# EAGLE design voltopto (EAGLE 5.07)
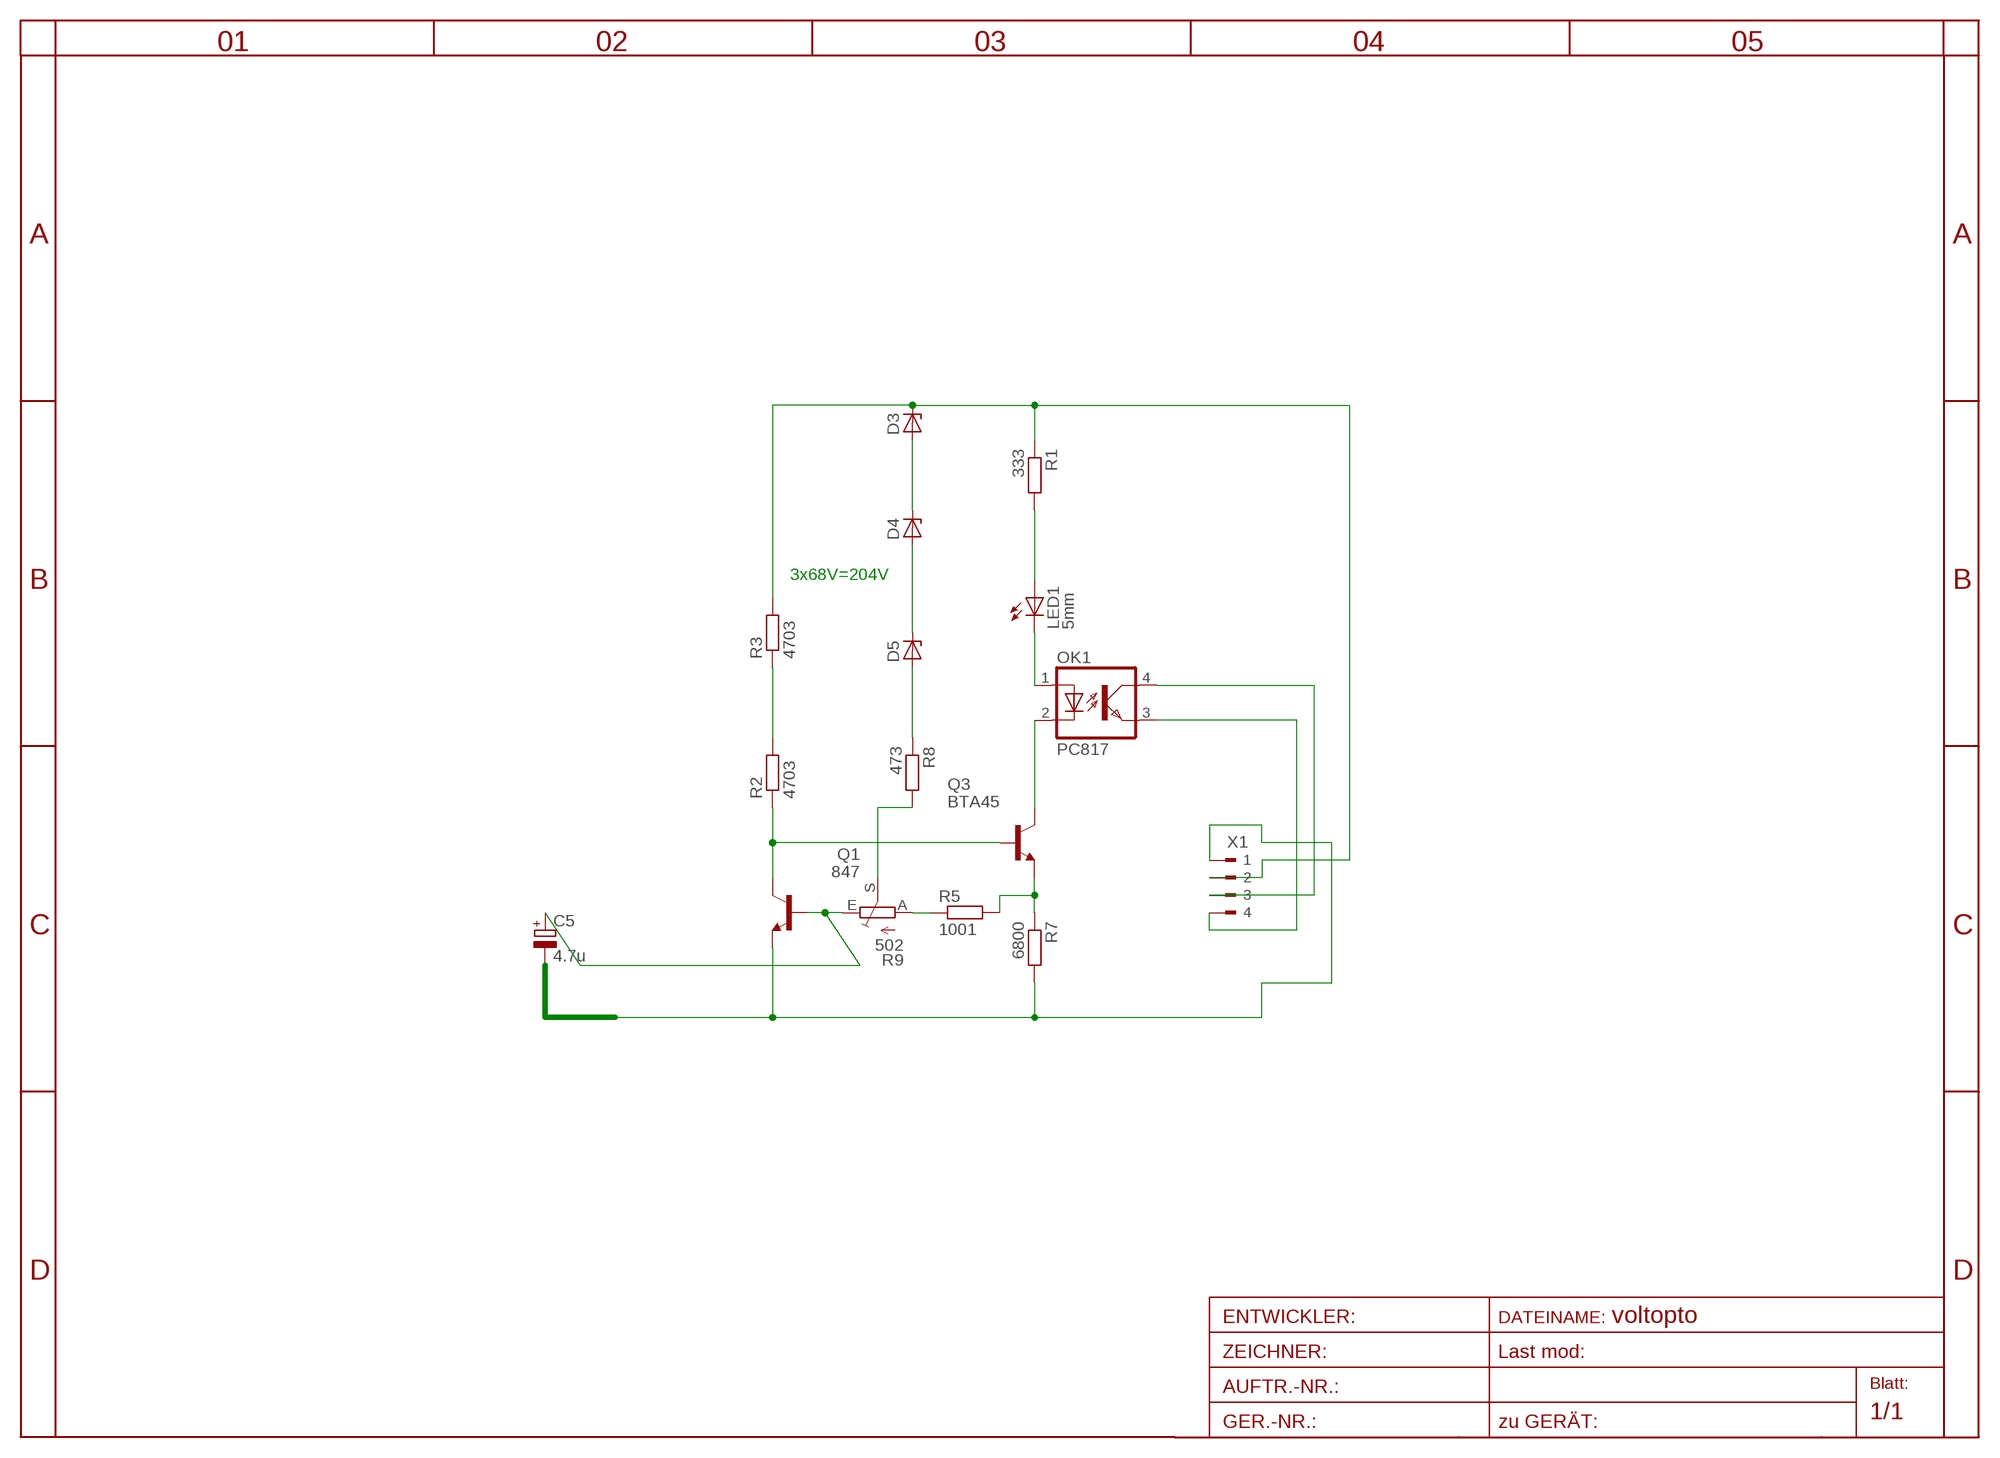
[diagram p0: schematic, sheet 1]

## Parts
C5  4.7u  CPOL-EUSMCA  [SMC_A]
D3  ZENER-DIODESOD80C  [SOD80C]
D4  ZENER-DIODESOD80C  [SOD80C]
D5  ZENER-DIODESOD80C  [SOD80C]
LED1  5mm  LED5MM  [LED5MM]
OK1  PC817  [DIL04]
Q1  847  BC848ALT1SMD  [SOT23]
Q3  BTA45  BC848ALT1SMD  [SOT23]
R1  333  R-EU_R1206  [R1206]
R2  4703  R-EU_R1206  [R1206]
R3  4703  R-EU_R1206  [R1206]
R5  1001  R-EU_R1206  [R1206]
R7  6800  R-EU_R1206  [R1206]
R8  473  R-EU_R1206  [R1206]
R9  502  TRIM_EU-S64W  [S64W]
X1  90-4  [90-4]

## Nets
A: LED1.A R1.2
AP: R5.1 R9.A
E: C5.+ Q1.1(B) R9.E
IN: D3.C R1.1 R3.2 X1.2
K: LED1.K(C) OK1.1(A)
N$3: R2.2 R3.1
N$8: Q3.2(E) R5.2 R7.1
N$13: D5.A R8.1
N$14: D4.A D5.C
N$15: D3.A D4.C
N$17: OK1.3(EMIT) X1.4
N$20: Q1.3(C) Q3.1(B) R2.1
N$21: OK1.2(C) Q3.3(C)
OUT-: OK1.4(COL) X1.3
S: R8.2 R9.S
V-: C5.- Q1.2(E) R7.2 X1.1

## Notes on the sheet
- 3x68V=204V

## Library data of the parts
C5 = rcl:CPOL-EU: POLARIZED CAPACITOR, European symbol
D3-D5 = diode:ZENER-DIODE: Z-Diode
LED1 = led:LED: LED
OK1 = optocoupler:PC817: SHARP OPTO COUPLER
Q1 Q3 = transistor-npn:BC848*: NPN Transistor
R1-R3 R5 R7 R8 = rcl:R-EU_: RESISTOR, European symbol
R9 = pot:TRIM_EU-: POTENTIOMETER
X1 = con-weidmueller-sl35:90-4: WEIDMUELLER CLAMP CONNECTOR

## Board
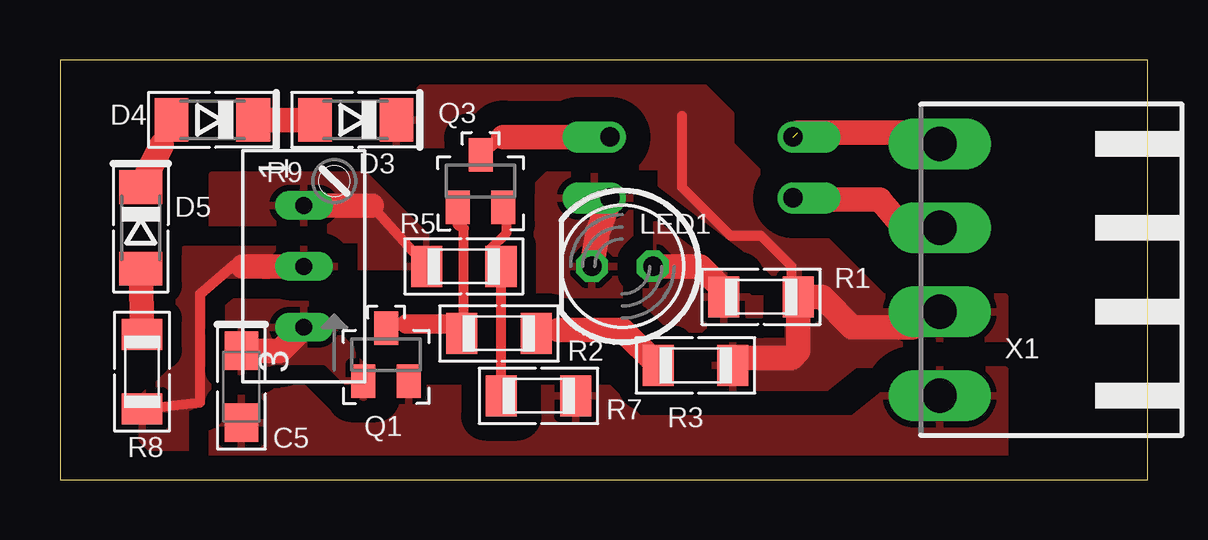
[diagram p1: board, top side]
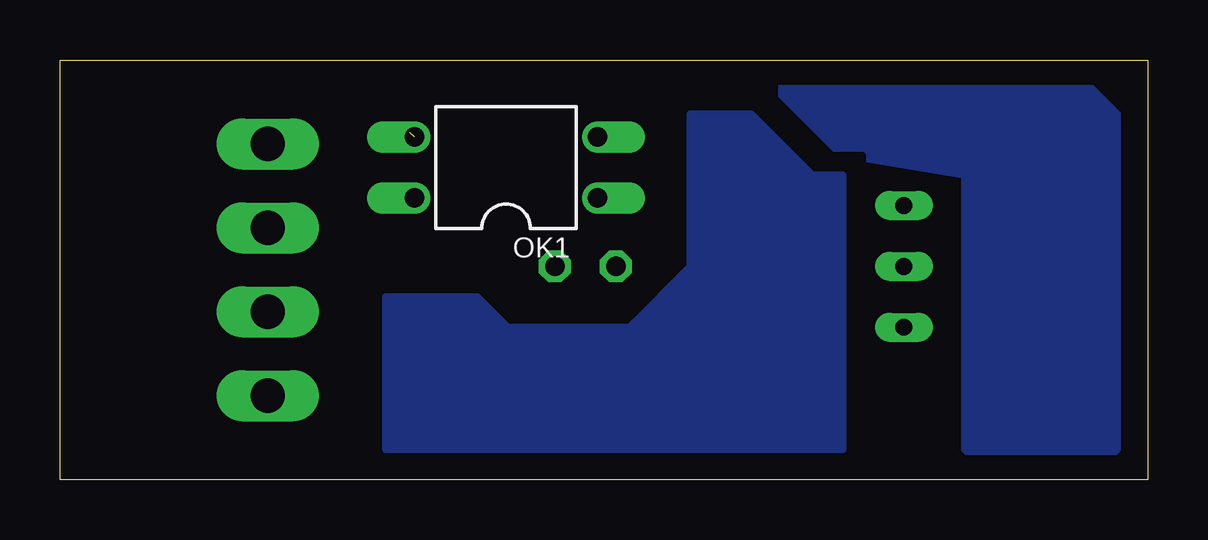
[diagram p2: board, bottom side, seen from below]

Size 45.32 x 17.5 mm. Coordinates in mm from the lower left corner, seen from the top.
Outline: 0,0 45.32,0 45.32,17.5 0,17.5 0,0
Copper layers (1*16): Top 0.035mm / dielectric 1.5mm / Bottom 0.035mm
Design rules "default *": minimum track width 10mil, minimum drill 20mil, track to track 8mil, track to pad 8mil, pad to pad 8mil, via to via 8mil, smd to smd 8mil, copper to edge 40mil, drill to drill 8mil, minimum pad ring 10mil, minimum via ring 8mil, stop-mask expansion 4mil, vias tented up to drill 0mil, thermal gap 10mil

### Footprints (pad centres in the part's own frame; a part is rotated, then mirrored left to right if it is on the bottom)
SMC_A = smd 1.6 x 1.4: + -1.5,0; - 1.5,0
SOD80C = smd 1.4 x 1.8: A 1.7,0; C -1.7,0
LED5MM = drill 0.813 octagon: A -1.27,0; K 1.27,0
DIL04 = drill 0.813 offset: 1 -1.27,-3.81; 2 1.27,-3.81; 3 1.27,3.81; 4 -1.27,3.81
SOT23 = smd 1 x 1.4: 1 -0.95,-1.1; 2 0.95,-1.1; 3 0,1.1
R1206 = smd 1.3 x 1.7: 1 -1.55,0; 2 1.55,0
S64W = drill 0.7 long: A 2.54,1.27; E -2.54,1.27; S 0,1.27
90-4 = drill 1.422 long: 1 -5.25,5.25; 2 -1.75,5.25; 3 1.75,5.25; 4 5.25,5.25

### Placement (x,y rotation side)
C5  7.56,3.87 270 top
D3  12.32,15 180 top
D4  6.35,15 180 top
D5  3.37,10.5 270 top
LED1  23.43,8.89 180 top
OK1  26.73,13.02 90 bottom
Q1  13.59,5.21 0 top
Q3  17.53,12.45 0 top
R1  29.21,7.62 180 top
R2  18.29,6.1 0 top
R3  26.48,4.76 0 top
R5  16.83,8.89 0 top
R7  19.94,3.49 0 top
R8  3.42,4.5 270 top
R9  11.43,8.89 90 top
X1  41.91,8.75 90 top

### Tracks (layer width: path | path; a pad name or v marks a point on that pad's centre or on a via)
A
  Top 1.016: R1.2 27.66,7.9 26.67,8.89 LED1.A
  pour Top (isolate 0.813, rank 4): 25.4,11.43 26.23,11.43 29.27,8.38 29.27,6.73 28.83,6.29 25.08,6.29 24.13,7.24 24.13,10.86 24.57,11.3
AP
  Top 0.406: 13,11.43 R5.1
  Top 1.016: R9.A 13,11.43
  pour Top (isolate 0.813, rank 4): 6.35,12.7 12.7,12.7 15.24,10.16 15.24,8.89 12.7,8.89 11.43,8.89 10.16,10.16 6.35,10.16
E
  Top 1.016: C5.+ 9.18,5.37 R9.E
  pour Top (isolate 0.813, rank 2): 7.62,7.62 9.97,7.62 12.95,4.64 12.95,3.56 12.83,3.43 9.46,3.43 8.57,4.32 7.37,4.32 6.98,4.7 6.98,7.18 7.18,7.37
IN
  Top 0.406: 25.92,15.18 25.92,12.18 27.94,10.16 29.21,10.16 30.48,8.89 30.48,7.9 R1.1
  Top 1.016: R3.2 28.35,5.08 30.48,5.08 30.76,5.36 R1.1 31.75,7.62 33.02,6.35 35.52,6.35 36.17,7 X1.2
  pour Top (isolate 1.016, rank 2): 39.37,7.62 34.29,7.62 27.94,13.97 27.94,15.24 26.67,16.51 15.24,16.51 13.97,15.24 13.97,13.97 22.86,13.97 29.21,9.14 30.35,8 30.35,5.78 27.31,5.71 27.31,4.45 27.94,2.54 31.75,2.54 35.56,5.08 39.37,5.08
K
  Top 1.016: OK1.1 22.42,10.31 LED1.K
  pour Top (isolate 0.813): 19.05,11.43 20.32,12.7 22.86,12.7 23.11,12.7 23.75,12.06 23.75,10.03 23.3,9.59 23.3,7.49 22.8,6.99 20.07,6.99 18.99,8.06
N$1
  pour Bottom (isolate 0.813, rank 4): 15.24,13.97 15.24,16.51 2.54,16.51 1.27,15.24 1.27,1.27 2.54,0 6.35,0 7.62,1.27 7.62,12.7
N$2
  pour Bottom (isolate 0.813, rank 3): 12.7,12.7 13.97,12.7 16.51,15.24 19.05,15.24 19.05,8.89 21.59,6.35 26.67,6.35 27.94,7.62 31.75,7.62 31.75,1.27 12.7,1.27
N$3
  Top 0.406: R2.2 20.6,6.39 20.32,6.22 20.76,6.25
  Top 1.016: 20.76,6.25 23.43,6.25 R3.1
N$8
  Top 0.406: R7.1 18.39,8.43 R5.2 17.93,9.61 18.61,10.29 18.61,11.22 Q3.2
N$13
  Top 1.016: R8.1 D5.A
N$14
  Top 0.406: 4.24,13.97 D4.A
  Top 1.016: D5.C 4.24,13.97
N$15
  Top 0.406: 10.65,15 D3.A
  Top 1.016: D4.C 10.65,15
N$17  (1 unrouted)
  Top 0.406: 35.37,14.48 35.85,14
  Top 1.016: 35.85,14 X1.4 | 30.75,14.48 35.37,14.48
N$20
  Top 0.406: Q3.1 16.58,10.6 16.83,10.48 16.83,6.57 R2.1 16.45,6.67 16.26,6.5 | Q1.3 14.44,6.5
  Top 0.813: 14.44,6.5 16.26,6.5
N$21
  Top 0.406: Q3.3 18.48,14.29
  Top 1.016: 18.48,14.29 OK1.2
OUT-
  Top 0.406: OK1.4 30.73,11.68
  Top 1.016: X1.3 35.16,10.5 34.16,11.68 30.73,11.68
S
  Top 0.406: R8.2 5.84,3.21 5.84,7.75 7.22,8.93 7.62,8.89
  Top 1.016: 7.62,8.89 R9.S
  pour Top (isolate 0.813, rank 3): 5.21,9.59 10.92,9.59 11.43,9.33 11.43,8.51 10.8,7.87 7.24,7.87 6.79,7.43 6.79,2.29 5.84,1.33 3.75,1.33 3.43,1.65 3.43,3.43 3.62,3.62 3.75,3.62 4.89,4.76 4.89,9.53
V-
  Top 1.016: X1.1 36.58,3.5
  pour Top (isolate 1.016): 6.35,2.54 6.35,0 39.37,0 39.37,4.57 35.56,4.57 33.02,2.54 24.13,2.54 22.86,3.81 13.97,3.81 13.97,2.54 11.43,2.54 10.16,3.81 7.62,3.81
